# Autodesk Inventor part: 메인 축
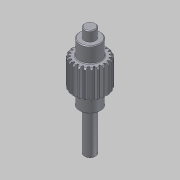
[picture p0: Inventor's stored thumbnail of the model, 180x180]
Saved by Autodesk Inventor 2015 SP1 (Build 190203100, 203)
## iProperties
Created: 2014-07
Part Number: 메인 축
Material: 강
Document SubType Name: Modeling
Designer: KYOUNG IL JANG
Categories: <?xml version="1.0" encoding="UTF-16"?> <MemberInstance><Categories><FamilyTemplate><FamilyTemplateParameter ValueType="xs:double" Id="1" ObjectReferenceKey="da
Density: 1 g/cm^3
Appearance: 강철
CustomPartVersion: 1
Company: 한국ATC센터
Author: KYOUNG IL JANG
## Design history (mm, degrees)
sketch "Sketch1"
  geometry: C1 r 12 at (0, 0)
  constraints: 1 centre point
  dimensions: "d0" = 24 diameter of C1 (= da_da)
extrude "Extrusion1" new body sketch "Sketch1" distance "d1" = 20 (= da_b); taper "d2" = 0 deg
workplane "Work Plane2"
feature "피치 지름" dims "d4" = 10, "d5" = 0
workplane "Work Plane8"
workplane "Work Plane9"
chamfer "모따기1" distance "d49" = 1; stored, may be unused: second distance "d50" = 2, angle "d51" = 45 deg
sketch "스케치3"
  geometry: C1 r 7.5 at (0, 0); 1 further point
  constraints: 1 centre point, 1 coincident
  dimensions: "d52" = 15 diameter of C1
extrude "돌출2" join sketch "스케치3" distance "d53" = 11; taper "d54" = 0 deg
sketch "스케치4"
  geometry: C1 r 4 at (0, 0); 1 further point
  constraints: 1 centre point, 1 coincident
  dimensions: "d55" = 8 diameter of C1
extrude "돌출3" join sketch "스케치4" distance "d56" = 7; taper "d57" = 0 deg
sketch "스케치5"
  geometry: C1 r 7.5 at (0, 0) reference; C2 r 7.5 at (0, 0) reference; 1 further point
extrude "돌출4" join sketch "스케치5" distance "d62" = 11; taper "d63" = 0 deg
sketch "스케치6"
  geometry: C1 r 4 at (0, 0); 1 further point
  constraints: 1 centre point, 1 coincident
  dimensions: "d64" = 8 diameter of C1
extrude "돌출5" join sketch "스케치6" distance "d65" = 30; taper "d66" = 0 deg
chamfer "모따기2" distance "d58" = 0.5; stored, may be unused: second distance "d59" = 2, angle "d60" = 45 deg
fillet "모깎기1" dims "d61" = 0.5
feature "스퍼 기어" dims "da_b" = 20, "da_d" = 22, "da_aw" = 31, "da_da" = 24, "da_df" = 19.5, "da_dw" = 22, angle "da_beta" = 0 deg, "da_lefttooth" = 0, "da_righttooth" = 0
body "Solid1"
sketch "Sketch2"
  geometry: C1 r 12 at (0, 0) reference; C2 r 11 at (0, 0)
  constraints: 1 centre point, 1 coincident
  dimensions: "d3" = 22 diameter of C2 (= da_dw)
body "Srf1"
node "투영된 루프1"
other parameters: "d16" = 31 (= da_aw), "d17" = 0, "d34" = 1.428 (computed from da_z), "d39" = 0, "d41" = 0, "d43" = 31 (= da_aw), "d46" = 31 (= da_aw), "d47" = 0, "d48" = 0
